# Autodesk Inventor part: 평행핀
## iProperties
IsCustomPart: 0
Created: 2009-02
Part Number: 평행핀
Material: 강, 연강
Description: 평행 핀
Document SubType Name: Modeling
Standard: KS B 1320
Designer: KYOUNG IL JANG
Standards Organization: KS
Language: ko-KR
Size Designation: B 5 x  20
Categories: <MemberInstance><Categories><Category DisplayName="조임쇠" InternalName="e4da775c-781d-43d5-af7c-5136215cf5a6" Mnemonic="FSTN"><Category DisplayName="핀" InternalNa
Density: 7.86 g/cm^3
Mass: 3.06605 g
Surface Area: 3.46755 cm^2
Volume: 0.390082 cm^3
Author: KYOUNG IL JANG
